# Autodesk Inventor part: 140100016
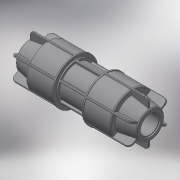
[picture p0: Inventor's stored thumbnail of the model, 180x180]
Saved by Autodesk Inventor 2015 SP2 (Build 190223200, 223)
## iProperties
Created: 2018-02
Part Number: 140100016
Material: Generic
Description: PLASSON L.14 COUPLER (SILVER) 16
Document SubType Name: Modeling
Designer: KIM
Mass: 70.8413 g
Surface Area: 212.163 cm^2
Volume: 70.8413 cm^3
Density: 1 g/cm^3
Appearance: Default
Author: KIM
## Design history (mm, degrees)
derived "140100.ipt"
feature "Solid1::140100.ipt"
tag "TaggingFeature1"
body "Solid1"
other parameters: "d30" = 1, "d36" = 1.05, "d65" = 37.83, "d77" = 14.72, "d93" = 24, "d95" = 15.75, "d96" = 1.05, "d97" = 17.6, "d100" = 29.25, "d102" = 39.9, "d103" = 1.05, "d107" = 62.65, "d113" = 39, "d114" = 1.6, "d115" = 0.8, "d117" = 0, "d126" = 3.9, "d127" = 0.39, "d129" = 360 deg, "d131" = 1.05, "d132" = 39, "d138" = 100 deg, "d139" = 33.15, "d141" = 105, "d142" = 16, "d144" = 0, "d145" = 16, "d147" = 0, "d149" = 1.95, "d150" = 0.975, "d152" = 0, "d153" = 0.39, "d155" = 360 deg, "E_" = 39, "d_" = 16, "H_" = 105
